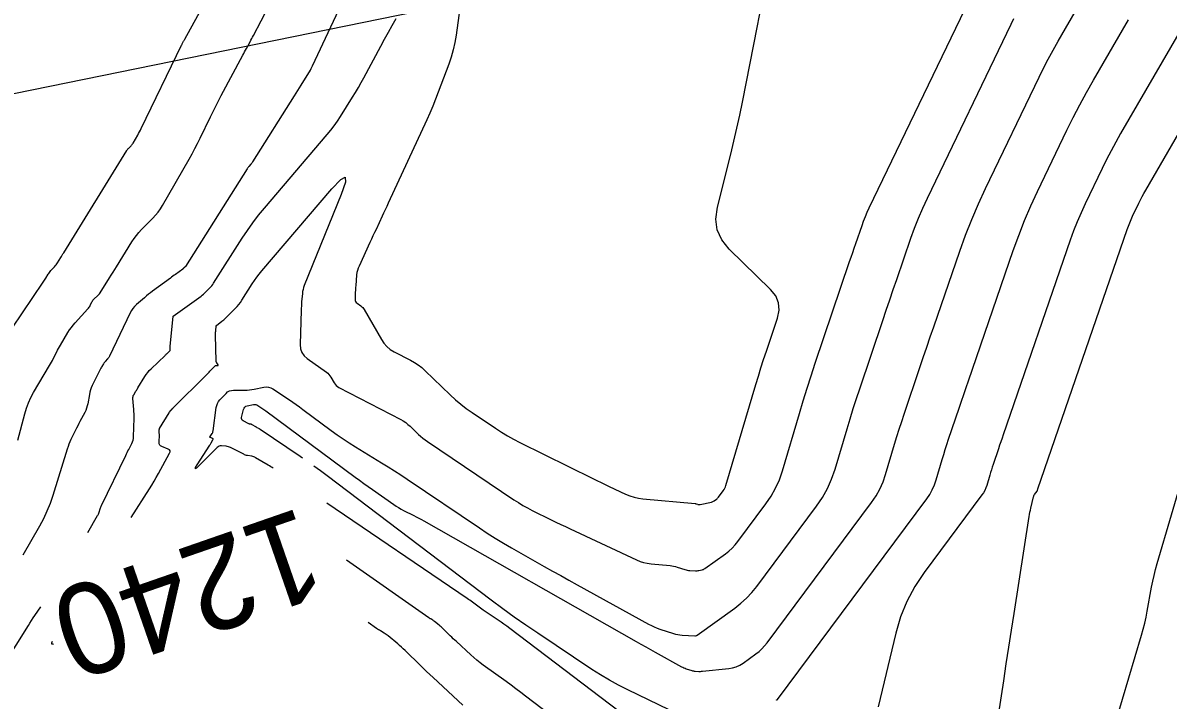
# Model space of a CAD drawing. Extents: x 658976 to 668726, y 639543 to 647196.
# Drawn here: x 662756.8 to 662832.1, y 642203.7 to 642248.2 of the extents above; entities that cross this region are included whole.
import ezdxf

# ---------------------------------------------------------------- set-up
doc = ezdxf.new("R2010")
doc.units = 0
for name, color, linetype in [('Ex_Contour Labels', 7, 'Continuous'), ('Ex_Major Contours', 7, 'Continuous'), ('Ex_Minor Contours', 7, 'Continuous'), ('R_Water', 7, 'Continuous')]:
    doc.layers.add(name, color=color, linetype=linetype)

msp = doc.modelspace()

# ---------------------------------------------------------------- linework, layer by layer
at = {"layer": 'Ex_Major Contours'}
for points in [[(662763.901, 642215.739), (662765.098, 642217.62), (662765.252, 642217.866), (662765.402, 642218.115), (662765.548, 642218.367), (662765.69, 642218.621), (662766.426, 642219.964), (662766.458, 642220.051), (662766.453, 642220.125), (662766.41, 642220.185), (662766.329, 642220.231), (662765.914, 642220.395), (662765.834, 642220.439), (662765.778, 642220.498), (662765.746, 642220.573), (662765.736, 642220.663), (662765.749, 642221.182), (662765.749, 642221.216), (662765.748, 642221.25), (662765.747, 642221.284), (662765.745, 642221.318), (662765.734, 642221.454), (662765.734, 642221.487), (662765.738, 642221.519), (662765.749, 642221.55), (662765.764, 642221.58), (662766.397, 642222.619), (662766.426, 642222.666), (662766.473, 642222.744), (662766.483, 642222.759), (662766.494, 642222.774), (662766.505, 642222.788), (662766.518, 642222.801), (662766.593, 642222.871), (662766.61, 642222.888), (662766.626, 642222.904), (662766.643, 642222.92), (662766.66, 642222.936), (662768.829, 642225.087), (662768.892, 642225.151), (662768.955, 642225.214), (662769.017, 642225.279), (662769.078, 642225.343), (662769.411, 642225.698), (662769.429, 642225.714), (662769.448, 642225.725), (662769.47, 642225.732), (662769.494, 642225.734), (662769.592, 642225.735), (662769.612, 642225.737), (662769.622, 642225.745), (662769.622, 642225.758), (662769.613, 642225.775), (662769.53, 642225.892), (662769.514, 642225.919), (662769.502, 642225.948), (662769.495, 642225.978), (662769.492, 642226.009), (662769.448, 642227.728), (662769.447, 642227.791), (662769.448, 642227.854), (662769.451, 642227.917), (662769.456, 642227.98), (662769.491, 642228.355), (662769.492, 642228.358), (662769.497, 642228.363), (662769.867, 642228.63), (662769.928, 642228.676), (662769.986, 642228.724), (662770.043, 642228.774), (662770.098, 642228.827), (662770.74, 642229.474), (662770.862, 642229.602), (662770.975, 642229.737), (662771.081, 642229.878), (662771.18, 642230.025), (662771.852, 642231.084), (662771.999, 642231.307), (662772.154, 642231.525), (662772.317, 642231.738), (662772.487, 642231.945), (662777.096, 642237.344), (662777.681, 642237.961), (662777.979, 642238.104), (662777.988, 642237.774), (662777.71, 642236.971), (662775.283, 642230.983), (662775.236, 642230.855), (662775.2, 642230.724), (662775.173, 642230.591), (662775.156, 642230.456), (662775.107, 642229.91), (662775.096, 642229.774), (662775.087, 642229.637), (662775.08, 642229.5), (662775.075, 642229.364), (662775.01, 642227.106), (662775.033, 642226.827), (662775.118, 642226.579), (662775.265, 642226.362), (662775.475, 642226.176), (662776.738, 642225.28), (662776.824, 642225.213), (662776.901, 642225.137), (662776.969, 642225.053), (662777.028, 642224.962), (662777.248, 642224.579), (662777.308, 642224.489), (662777.379, 642224.411), (662777.461, 642224.343), (662777.554, 642224.287), (662781.628, 642222.172), (662781.793, 642222.079), (662781.951, 642221.974), (662782.1, 642221.858), (662782.242, 642221.731), (662782.792, 642221.2), (662782.932, 642221.071), (662783.078, 642220.948), (662783.229, 642220.832), (662783.385, 642220.722), (662789.068, 642216.901), (662789.359, 642216.712), (662789.657, 642216.533), (662789.96, 642216.364), (662790.269, 642216.205), (662791.516, 642215.589), (662791.828, 642215.436), (662792.141, 642215.285), (662792.455, 642215.135), (662792.769, 642214.987), (662797.132, 642212.946), (662797.361, 642212.851), (662797.595, 642212.776), (662797.835, 642212.722), (662798.081, 642212.689), (662799.338, 642212.571), (662799.454, 642212.557), (662799.569, 642212.536), (662799.682, 642212.509), (662799.794, 642212.476), (662800.304, 642212.309), (662800.383, 642212.286), (662800.462, 642212.269), (662800.543, 642212.257), (662800.625, 642212.25), (662801.012, 642212.232), (662801.065, 642212.231), (662801.119, 642212.234), (662801.172, 642212.24), (662801.225, 642212.249), (662801.436, 642212.293), (662801.488, 642212.307), (662801.537, 642212.326), (662801.585, 642212.35), (662801.629, 642212.379), (662802.968, 642213.347), (662803.198, 642213.526), (662803.412, 642213.722), (662803.611, 642213.933), (662803.793, 642214.161), (662805.637, 642216.636), (662805.978, 642217.139), (662806.272, 642217.666), (662806.518, 642218.217), (662806.716, 642218.792), (662807.84, 642222.58), (662808.089, 642223.406), (662808.346, 642224.229), (662808.611, 642225.05), (662808.883, 642225.869), (662811.142, 642232.556), (662811.243, 642232.853), (662811.344, 642233.149), (662811.445, 642233.446), (662811.547, 642233.742), (662811.955, 642234.927), (662812.061, 642235.222), (662812.176, 642235.513), (662812.299, 642235.801), (662812.431, 642236.085), (662819.914, 642251.643)], [(662820.385, 642199.223), (662821.27, 642205), (662821.441, 642206.108), (662821.611, 642207.216), (662821.783, 642208.324), (662821.955, 642209.432), (662822.946, 642215.799), (662822.969, 642215.938), (662822.994, 642216.077), (662823.023, 642216.215), (662823.055, 642216.353), (662823.23, 642217.086), (662823.243, 642217.13), (662823.26, 642217.172), (662823.281, 642217.212), (662823.307, 642217.25), (662823.463, 642217.461), (662823.467, 642217.467), (662823.471, 642217.473), (662823.474, 642217.48), (662823.476, 642217.487), (662823.485, 642217.515), (662823.489, 642217.529), (662823.494, 642217.543), (662823.511, 642217.595), (662823.521, 642217.624), (662829.386, 642234.66), (662829.467, 642234.884), (662829.555, 642235.106), (662829.648, 642235.325), (662829.749, 642235.541), (662830.162, 642236.402), (662830.268, 642236.616), (662830.377, 642236.827), (662830.491, 642237.037), (662830.609, 642237.245), (662836.073, 642246.667)], [(662794.59, 642200.385), (662789.829, 642203.998), (662789.512, 642204.237), (662789.194, 642204.474), (662788.874, 642204.71), (662788.553, 642204.944), (662787.05, 642206.033), (662786.84, 642206.19), (662786.634, 642206.353), (662786.433, 642206.522), (662786.237, 642206.697), (662785.282, 642207.574), (662785.18, 642207.67), (662785.078, 642207.766), (662784.977, 642207.862), (662784.877, 642207.96), (662784.39, 642208.438), (662784.333, 642208.493), (662784.275, 642208.546), (662784.216, 642208.598), (662784.155, 642208.649), (662783.846, 642208.903), (662783.817, 642208.926), (662783.787, 642208.947), (662783.757, 642208.968), (662783.726, 642208.987), (662783.599, 642209.063), (662783.568, 642209.082), (662783.537, 642209.102), (662783.506, 642209.123), (662783.475, 642209.143), (662778.055, 642212.94)], [(662758.798, 642207.427), (662758.761, 642207.409), (662758.67, 642207.408), (662758.673, 642207.499), (662758.733, 642207.613)]]:
    msp.add_lwpolyline(points, dxfattribs=at)
at = {"layer": 'Ex_Minor Contours'}
for points in [[(662786.347, 642255.341), (662785.265, 642247.433), (662785.185, 642246.948), (662785.078, 642246.47), (662784.945, 642245.999), (662784.785, 642245.535), (662784.09, 642243.69), (662783.912, 642243.231), (662783.726, 642242.775), (662783.532, 642242.322), (662783.329, 642241.873), (662780.797, 642236.394), (662780.698, 642236.179), (662780.598, 642235.964), (662780.498, 642235.749), (662780.398, 642235.534), (662779.996, 642234.675), (662779.896, 642234.461), (662779.796, 642234.246), (662779.696, 642234.031), (662779.597, 642233.816), (662778.879, 642232.263), (662778.821, 642232.122), (662778.776, 642231.977), (662778.743, 642231.83), (662778.723, 642231.679), (662778.661, 642230.973), (662778.652, 642230.868), (662778.645, 642230.762), (662778.64, 642230.657), (662778.636, 642230.551), (662778.622, 642230.077), (662778.628, 642230.001), (662778.651, 642229.934), (662778.691, 642229.875), (662778.748, 642229.825), (662779.009, 642229.64), (662779.071, 642229.591), (662779.126, 642229.536), (662779.176, 642229.475), (662779.219, 642229.409), (662780.355, 642227.433), (662780.519, 642227.187), (662780.713, 642226.972), (662780.936, 642226.788), (662781.189, 642226.634), (662782.257, 642226.08), (662782.518, 642225.932), (662782.766, 642225.767), (662783.001, 642225.585), (662783.224, 642225.385), (662784.874, 642223.794), (662785.214, 642223.48), (662785.567, 642223.182), (662785.932, 642222.899), (662786.311, 642222.633), (662787.849, 642221.598), (662788.238, 642221.347), (662788.634, 642221.108), (662789.038, 642220.883), (662789.45, 642220.671), (662794.26, 642218.296), (662794.527, 642218.165), (662794.795, 642218.036), (662795.063, 642217.908), (662795.333, 642217.781), (662796.411, 642217.276), (662796.684, 642217.163), (662796.964, 642217.073), (662797.25, 642217.009), (662797.543, 642216.969), (662800.989, 642216.646), (662801.009, 642216.644), (662801.027, 642216.64), (662801.046, 642216.636), (662801.065, 642216.63), (662801.149, 642216.603), (662801.162, 642216.599), (662801.175, 642216.596), (662801.188, 642216.594), (662801.202, 642216.593), (662801.256, 642216.591), (662801.27, 642216.59), (662801.283, 642216.591), (662801.297, 642216.593), (662801.31, 642216.595), (662802.055, 642216.752), (662802.102, 642216.764), (662802.146, 642216.781), (662802.188, 642216.802), (662802.229, 642216.828), (662802.386, 642216.942), (662802.424, 642216.972), (662802.459, 642217.004), (662802.492, 642217.039), (662802.522, 642217.076), (662802.826, 642217.485), (662802.883, 642217.568), (662802.931, 642217.655), (662802.972, 642217.746), (662803.005, 642217.841), (662804.973, 642224.477), (662805.139, 642225.025), (662805.309, 642225.572), (662805.485, 642226.117), (662805.666, 642226.66), (662806.399, 642228.83), (662806.508, 642229.355), (662806.469, 642229.844), (662806.282, 642230.297), (662805.946, 642230.715), (662803.224, 642233.374), (662802.733, 642233.978), (662802.439, 642234.639), (662802.343, 642235.355), (662802.446, 642236.127), (662803.324, 642239.62), (662803.532, 642240.47), (662803.729, 642241.323), (662803.914, 642242.178), (662804.089, 642243.036), (662805.078, 642248.063), (662805.308, 642249.184)], [(662754.696, 642226.155), (662758.12, 642231.208), (662758.162, 642231.27), (662758.203, 642231.334), (662758.243, 642231.397), (662758.282, 642231.462), (662758.437, 642231.721), (662758.477, 642231.784), (662758.521, 642231.846), (662758.567, 642231.905), (662758.616, 642231.962), (662758.85, 642232.217), (662758.904, 642232.28), (662758.955, 642232.344), (662759.004, 642232.411), (662759.049, 642232.48), (662759.261, 642232.818), (662759.311, 642232.898), (662759.361, 642232.978), (662759.411, 642233.058), (662759.46, 642233.138), (662763.614, 642239.857), (662763.643, 642239.901), (662763.674, 642239.944), (662763.708, 642239.984), (662763.744, 642240.022), (662763.892, 642240.173), (662763.928, 642240.211), (662763.961, 642240.252), (662763.991, 642240.295), (662764.019, 642240.339), (662764.328, 642240.878), (662764.388, 642240.983), (662764.445, 642241.09), (662764.501, 642241.197), (662764.555, 642241.306), (662767.209, 642246.774), (662767.226, 642246.808), (662767.243, 642246.841), (662767.26, 642246.875), (662767.278, 642246.908), (662767.348, 642247.041), (662767.366, 642247.074), (662767.384, 642247.107), (662767.402, 642247.141), (662767.42, 642247.174), (662769.374, 642250.747)], [(662756.45, 642220.825), (662756.895, 642222.554), (662757.004, 642222.921), (662757.138, 642223.278), (662757.297, 642223.623), (662757.482, 642223.959), (662758.535, 642225.719), (662758.599, 642225.829), (662758.661, 642225.94), (662758.721, 642226.053), (662758.778, 642226.166), (662759.004, 642226.623), (662759.062, 642226.737), (662759.122, 642226.849), (662759.184, 642226.961), (662759.248, 642227.071), (662759.74, 642227.894), (662759.848, 642228.064), (662759.964, 642228.229), (662760.088, 642228.387), (662760.221, 642228.54), (662761.057, 642229.457), (662761.1, 642229.506), (662761.138, 642229.559), (662761.172, 642229.614), (662761.202, 642229.672), (662761.315, 642229.909), (662761.346, 642229.966), (662761.382, 642230.019), (662761.424, 642230.068), (662761.471, 642230.113), (662761.683, 642230.297), (662761.733, 642230.343), (662761.779, 642230.393), (662761.821, 642230.446), (662761.859, 642230.503), (662762.476, 642231.487), (662762.591, 642231.67), (662762.705, 642231.854), (662762.82, 642232.038), (662762.933, 642232.222), (662763.94, 642233.851), (662764.084, 642234.07), (662764.24, 642234.28), (662764.408, 642234.48), (662764.586, 642234.672), (662765.326, 642235.42), (662765.504, 642235.612), (662765.668, 642235.814), (662765.819, 642236.027), (662765.957, 642236.249), (662767.709, 642239.299), (662767.9, 642239.638), (662768.085, 642239.981), (662768.265, 642240.327), (662768.438, 642240.676), (662769.118, 642242.078), (662769.29, 642242.428), (662769.465, 642242.776), (662769.644, 642243.122), (662769.825, 642243.467), (662771.244, 642246.135), (662771.302, 642246.243), (662771.36, 642246.351), (662771.418, 642246.459), (662771.476, 642246.566), (662771.712, 642246.996), (662771.77, 642247.104), (662771.828, 642247.212), (662771.885, 642247.32), (662771.942, 642247.429), (662773.951, 642251.304)], [(662778.216, 642250.546), (662775.799, 642245.406), (662775.778, 642245.362), (662775.756, 642245.317), (662775.714, 642245.229), (662775.703, 642245.207), (662775.692, 642245.185), (662775.68, 642245.164), (662775.667, 642245.143), (662775.054, 642244.148), (662774.947, 642243.976), (662774.84, 642243.803), (662774.732, 642243.631), (662774.624, 642243.459), (662771.885, 642239.117), (662771.858, 642239.077), (662771.83, 642239.037), (662771.801, 642238.998), (662771.77, 642238.961), (662771.644, 642238.813), (662771.613, 642238.776), (662771.583, 642238.737), (662771.555, 642238.698), (662771.529, 642238.657), (662767.459, 642232.239), (662767.448, 642232.222), (662767.435, 642232.205), (662767.422, 642232.189), (662767.407, 642232.174), (662767.348, 642232.114), (662767.333, 642232.1), (662767.317, 642232.086), (662767.301, 642232.073), (662767.284, 642232.06), (662766.81, 642231.718), (662766.726, 642231.657), (662766.641, 642231.596), (662766.557, 642231.534), (662766.473, 642231.472), (662765.306, 642230.617), (662765.167, 642230.513), (662765.031, 642230.407), (662764.897, 642230.297), (662764.765, 642230.185), (662764.241, 642229.732), (662764.118, 642229.613), (662764.008, 642229.484), (662763.912, 642229.343), (662763.831, 642229.193), (662762.473, 642226.349), (662762.447, 642226.299), (662762.418, 642226.252), (662762.385, 642226.207), (662762.349, 642226.164), (662762.19, 642225.991), (662762.157, 642225.952), (662762.125, 642225.912), (662762.096, 642225.87), (662762.069, 642225.827), (662761.964, 642225.651), (662761.938, 642225.607), (662761.913, 642225.562), (662761.889, 642225.517), (662761.866, 642225.471), (662761.34, 642224.407), (662761.276, 642224.267), (662761.223, 642224.123), (662761.181, 642223.976), (662761.148, 642223.825), (662761.039, 642223.216), (662761.006, 642223.065), (662760.962, 642222.918), (662760.906, 642222.776), (662760.84, 642222.637), (662760.53, 642222.048), (662760.455, 642221.904), (662760.381, 642221.759), (662760.309, 642221.614), (662760.237, 642221.468), (662759.94, 642220.856), (662759.87, 642220.704), (662759.806, 642220.549), (662759.747, 642220.393), (662759.694, 642220.234), (662758.746, 642217.189), (662758.568, 642216.665), (662758.361, 642216.154), (662758.127, 642215.654), (662757.866, 642215.167), (662756.781, 642213.269)], [(662775.157, 642219.644), (662775.019, 642219.739), (662772.382, 642221.526), (662772.359, 642221.542), (662772.336, 642221.556), (662772.311, 642221.57), (662772.287, 642221.584), (662772.189, 642221.637), (662772.164, 642221.65), (662772.14, 642221.664), (662772.116, 642221.678), (662772.092, 642221.692), (662771.853, 642221.835), (662771.836, 642221.844), (662771.818, 642221.852), (662771.799, 642221.858), (662771.78, 642221.862), (662771.702, 642221.875), (662771.682, 642221.879), (662771.663, 642221.884), (662771.645, 642221.891), (662771.627, 642221.899), (662771.258, 642222.088), (662771.201, 642222.128), (662771.166, 642222.177), (662771.152, 642222.236), (662771.159, 642222.305), (662771.288, 642222.842), (662771.32, 642222.928), (662771.37, 642222.995), (662771.439, 642223.043), (662771.526, 642223.072), (662771.949, 642223.16), (662772.024, 642223.168), (662772.096, 642223.162), (662772.166, 642223.141), (662772.232, 642223.105), (662772.493, 642222.931), (662772.558, 642222.887), (662772.622, 642222.842), (662772.686, 642222.797), (662772.749, 642222.75), (662778.628, 642218.389), (662778.909, 642218.182), (662779.191, 642217.977), (662779.475, 642217.774), (662779.76, 642217.574), (662781.168, 642216.591), (662781.324, 642216.486), (662781.483, 642216.386), (662781.645, 642216.293), (662781.811, 642216.204), (662782.48, 642215.862), (662782.647, 642215.776), (662782.813, 642215.688), (662782.978, 642215.598), (662783.142, 642215.506), (662797.108, 642207.58), (662797.419, 642207.404), (662797.731, 642207.229), (662798.044, 642207.055), (662798.357, 642206.881), (662800.091, 642205.926), (662800.164, 642205.888), (662800.239, 642205.853), (662800.316, 642205.822), (662800.395, 642205.794), (662800.757, 642205.675), (662800.814, 642205.659), (662800.87, 642205.647), (662800.928, 642205.638), (662800.986, 642205.633), (662801.221, 642205.622), (662801.279, 642205.621), (662801.338, 642205.621), (662801.396, 642205.624), (662801.455, 642205.628), (662803.192, 642205.8), (662803.446, 642205.842), (662803.687, 642205.915), (662803.916, 642206.02), (662804.134, 642206.157), (662804.979, 642206.768), (662805.183, 642206.928), (662805.374, 642207.102), (662805.55, 642207.29), (662805.713, 642207.492), (662812.588, 642216.725), (662812.878, 642217.152), (662813.128, 642217.601), (662813.337, 642218.069), (662813.506, 642218.558), (662814.098, 642220.554), (662814.248, 642221.052), (662814.403, 642221.549), (662814.563, 642222.044), (662814.727, 642222.538), (662815.757, 642225.587), (662815.985, 642226.259), (662816.214, 642226.931), (662816.443, 642227.603), (662816.674, 642228.274), (662818.387, 642233.25), (662818.765, 642234.297), (662819.172, 642235.332), (662819.61, 642236.354), (662820.078, 642237.364), (662823.593, 642244.673), (662823.891, 642245.276), (662824.2, 642245.874), (662824.52, 642246.465), (662824.852, 642247.051), (662826.203, 642249.381)], [(662761.057, 642214.753), (662761.688, 642215.856), (662761.717, 642215.909), (662761.742, 642215.963), (662761.765, 642216.019), (662761.784, 642216.076), (662761.856, 642216.307), (662761.875, 642216.364), (662761.896, 642216.421), (662761.919, 642216.476), (662761.945, 642216.531), (662763.536, 642219.813), (662763.585, 642219.913), (662763.635, 642220.014), (662763.686, 642220.113), (662763.738, 642220.213), (662763.946, 642220.609), (662763.992, 642220.71), (662764.026, 642220.814), (662764.047, 642220.921), (662764.056, 642221.031), (662764.086, 642222.272), (662764.087, 642222.415), (662764.085, 642222.557), (662764.079, 642222.699), (662764.069, 642222.841), (662764.011, 642223.561), (662764.011, 642223.625), (662764.02, 642223.687), (662764.039, 642223.747), (662764.069, 642223.804), (662764.206, 642224.029), (662764.24, 642224.085), (662764.274, 642224.141), (662764.308, 642224.197), (662764.342, 642224.254), (662764.793, 642224.997), (662764.883, 642225.136), (662764.983, 642225.268), (662765.09, 642225.393), (662765.207, 642225.512), (662766.125, 642226.384), (662766.16, 642226.418), (662766.195, 642226.452), (662766.23, 642226.486), (662766.265, 642226.52), (662766.436, 642226.69), (662766.452, 642226.709), (662766.463, 642226.729), (662766.469, 642226.752), (662766.471, 642226.776), (662766.468, 642226.878), (662766.468, 642226.903), (662766.469, 642226.928), (662766.47, 642226.953), (662766.472, 642226.979), (662766.655, 642228.959), (662766.657, 642228.961), (662768.494, 642230.286), (662768.573, 642230.345), (662768.649, 642230.408), (662768.723, 642230.474), (662768.794, 642230.543), (662769.074, 642230.824), (662769.142, 642230.896), (662769.205, 642230.971), (662769.265, 642231.05), (662769.32, 642231.132), (662771.198, 642234.095), (662771.538, 642234.61), (662771.895, 642235.112), (662772.27, 642235.601), (662772.662, 642236.078), (662776.786, 642240.909), (662777.022, 642241.195), (662777.247, 642241.49), (662777.462, 642241.793), (662777.666, 642242.103), (662778.459, 642243.362), (662778.655, 642243.678), (662778.845, 642243.997), (662779.028, 642244.32), (662779.206, 642244.647), (662780.318, 642246.728), (662780.563, 642247.183), (662780.813, 642247.636), (662781.067, 642248.086), (662781.325, 642248.535)], [(662773.243, 642218.98), (662773.16, 642219.025), (662773.075, 642219.073), (662772.991, 642219.121), (662772.908, 642219.17), (662772.08, 642219.667), (662772.02, 642219.699), (662771.958, 642219.725), (662771.893, 642219.746), (662771.827, 642219.76), (662771.555, 642219.805), (662771.488, 642219.819), (662771.422, 642219.837), (662771.359, 642219.861), (662771.297, 642219.89), (662770.438, 642220.33), (662770.367, 642220.362), (662770.293, 642220.387), (662770.218, 642220.405), (662770.141, 642220.414), (662769.827, 642220.439), (662769.752, 642220.438), (662769.682, 642220.421), (662769.617, 642220.388), (662769.559, 642220.341), (662768.332, 642219.114), (662768.182, 642218.974), (662768.117, 642218.94), (662768.136, 642219.011), (662768.24, 642219.188), (662769.064, 642220.483), (662769.09, 642220.524), (662769.115, 642220.566), (662769.14, 642220.609), (662769.164, 642220.652), (662769.272, 642220.849), (662769.282, 642220.877), (662769.281, 642220.901), (662769.267, 642220.921), (662769.241, 642220.936), (662769.111, 642220.987), (662769.086, 642221.002), (662769.073, 642221.02), (662769.073, 642221.043), (662769.087, 642221.069), (662769.214, 642221.249), (662769.239, 642221.289), (662769.259, 642221.332), (662769.273, 642221.377), (662769.283, 642221.423), (662769.495, 642222.962), (662769.525, 642223.102), (662769.575, 642223.233), (662769.645, 642223.354), (662769.735, 642223.465), (662770.135, 642223.892), (662770.241, 642223.985), (662770.358, 642224.052), (662770.487, 642224.092), (662770.627, 642224.106), (662771.353, 642224.109), (662771.515, 642224.114), (662771.675, 642224.126), (662771.835, 642224.147), (662771.994, 642224.176), (662772.627, 642224.307), (662772.783, 642224.324), (662772.932, 642224.311), (662773.076, 642224.267), (662773.213, 642224.193), (662774.3, 642223.468), (662774.525, 642223.316), (662774.748, 642223.161), (662774.969, 642223.003), (662775.188, 642222.843), (662777.057, 642221.456), (662777.444, 642221.176), (662777.837, 642220.904), (662778.236, 642220.641), (662778.641, 642220.387), (662780.366, 642219.333), (662780.788, 642219.072), (662781.207, 642218.806), (662781.623, 642218.536), (662782.036, 642218.261), (662786.798, 642215.05), (662787.316, 642214.709), (662787.839, 642214.377), (662788.369, 642214.056), (662788.905, 642213.745), (662791.063, 642212.52), (662791.603, 642212.215), (662792.144, 642211.911), (662792.686, 642211.609), (662793.228, 642211.309), (662797.925, 642208.722), (662798.106, 642208.628), (662798.29, 642208.543), (662798.478, 642208.466), (662798.67, 642208.398), (662799.559, 642208.107), (662799.697, 642208.067), (662799.836, 642208.037), (662799.977, 642208.016), (662800.12, 642208.004), (662800.953, 642207.965), (662800.967, 642207.964), (662800.981, 642207.965), (662800.995, 642207.965), (662801.009, 642207.966), (662801.065, 642207.972), (662801.078, 642207.974), (662801.091, 642207.978), (662801.103, 642207.984), (662801.115, 642207.991), (662803.59, 642209.78), (662803.992, 642210.095), (662804.368, 642210.437), (662804.715, 642210.808), (662805.036, 642211.206), (662808.963, 642216.48), (662809.349, 642217.048), (662809.681, 642217.643), (662809.958, 642218.265), (662810.182, 642218.915), (662810.969, 642221.567), (662811.169, 642222.229), (662811.375, 642222.889), (662811.587, 642223.547), (662811.805, 642224.203), (662813.321, 642228.689), (662813.549, 642229.365), (662813.779, 642230.04), (662814.01, 642230.715), (662814.242, 642231.39), (662815.171, 642234.089), (662815.413, 642234.76), (662815.674, 642235.422), (662815.955, 642236.077), (662816.254, 642236.724), (662821.754, 642248.158), (662821.937, 642248.529)], [(662806.329, 642203.73), (662806.336, 642203.733), (662806.342, 642203.738), (662806.368, 642203.756), (662806.374, 642203.761), (662806.38, 642203.766), (662806.385, 642203.772), (662806.39, 642203.778), (662816.213, 642216.97), (662816.408, 642217.257), (662816.576, 642217.558), (662816.716, 642217.873), (662816.829, 642218.201), (662817.227, 642219.541), (662817.328, 642219.875), (662817.432, 642220.209), (662817.539, 642220.541), (662817.649, 642220.873), (662818.341, 642222.92), (662818.494, 642223.371), (662818.647, 642223.822), (662818.801, 642224.273), (662818.956, 642224.724), (662821.903, 642233.283), (662822.26, 642234.273), (662822.645, 642235.251), (662823.059, 642236.218), (662823.502, 642237.173), (662825.433, 642241.187), (662825.845, 642242.023), (662826.273, 642242.851), (662826.717, 642243.67), (662827.176, 642244.481), (662829.483, 642248.459)], [(662832.778, 642247.563), (662828.953, 642240.967), (662828.635, 642240.406), (662828.327, 642239.838), (662828.031, 642239.265), (662827.745, 642238.686), (662826.625, 642236.357), (662826.354, 642235.771), (662826.1, 642235.178), (662825.864, 642234.578), (662825.645, 642233.971), (662821.239, 642221.174), (662821.16, 642220.944), (662821.081, 642220.714), (662821.003, 642220.483), (662820.925, 642220.253), (662820.571, 642219.208), (662820.515, 642219.039), (662820.46, 642218.869), (662820.407, 642218.699), (662820.356, 642218.528), (662820.153, 642217.844), (662820.095, 642217.676), (662820.023, 642217.515), (662819.938, 642217.362), (662819.838, 642217.215), (662816.037, 642212.11), (662815.419, 642211.188), (662814.903, 642210.217), (662814.489, 642209.199), (662814.177, 642208.134), (662813.021, 642203.297)], [(662826.997, 642196.788), (662830.338, 642208.01), (662830.447, 642208.396), (662830.546, 642208.784), (662830.634, 642209.175), (662830.711, 642209.568), (662830.999, 642211.146), (662831.077, 642211.54), (662831.164, 642211.931), (662831.261, 642212.319), (662831.369, 642212.705), (662834.18, 642222.301)], [(662799.954, 642202.761), (662796.548, 642204.406), (662795.941, 642204.712), (662795.346, 642205.038), (662794.762, 642205.386), (662794.19, 642205.753), (662790.636, 642208.124), (662789.859, 642208.651), (662789.091, 642209.189), (662788.33, 642209.739), (662787.577, 642210.3), (662776.775, 642218.48), (662776.342, 642218.804), (662775.912, 642219.116)], [(662797.168, 642202.088), (662788.786, 642208.448), (662788.599, 642208.588), (662788.409, 642208.725), (662788.218, 642208.859), (662788.024, 642208.991), (662787.036, 642209.65), (662786.946, 642209.711), (662786.858, 642209.773), (662786.77, 642209.836), (662786.683, 642209.901), (662786.339, 642210.162), (662786.252, 642210.226), (662786.165, 642210.29), (662786.076, 642210.352), (662785.987, 642210.414), (662776.761, 642216.667)], [(662754.585, 642204.573), (662757.137, 642208.631), (662757.244, 642208.799), (662757.351, 642208.966), (662757.46, 642209.132), (662757.57, 642209.298), (662757.951, 642209.867)], [(662785.713, 642203.409), (662783.747, 642205.215), (662783.536, 642205.411), (662783.326, 642205.608), (662783.118, 642205.808), (662782.912, 642206.009), (662781.911, 642206.993), (662781.793, 642207.105), (662781.674, 642207.215), (662781.552, 642207.322), (662781.427, 642207.427), (662780.79, 642207.949), (662780.73, 642207.996), (662780.669, 642208.041), (662780.606, 642208.083), (662780.542, 642208.124), (662780.282, 642208.28), (662780.217, 642208.319), (662780.153, 642208.36), (662780.09, 642208.402), (662780.027, 642208.445), (662779.481, 642208.827)]]:
    msp.add_lwpolyline(points, dxfattribs=at)
at = {"layer": 'R_Water'}
msp.add_line((662444.532, 642179.939), (662827.779, 642258.226), dxfattribs=at)

# ---------------------------------------------------------------- texts
at = {"layer": 'Ex_Contour Labels'}
msp.add_text('1240', height=6, rotation=199.13183, dxfattribs=at).set_placement((662775.076, 642216.44))

doc.saveas('drawing.dxf')
